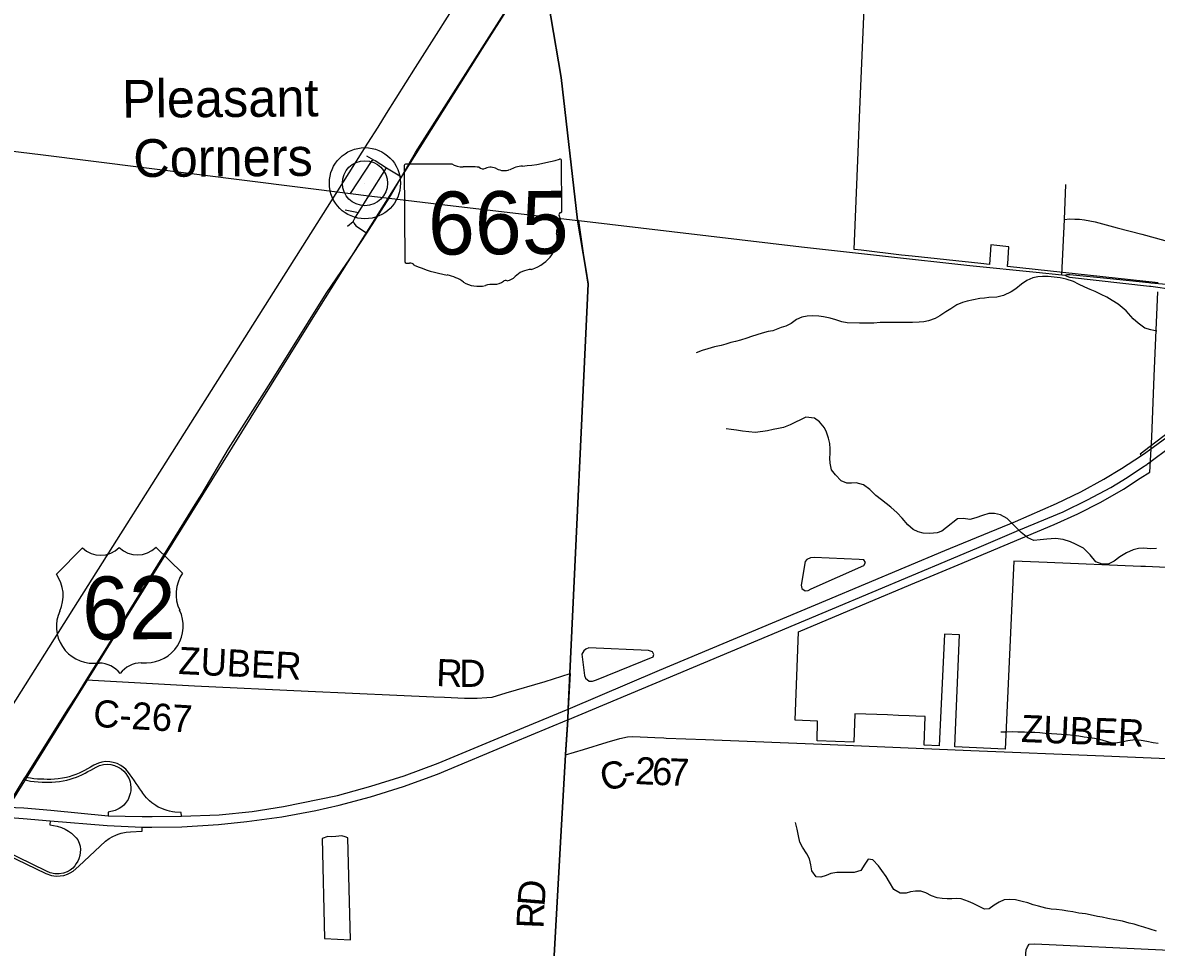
# Model space of a CAD drawing. Extents: x 114843 to 284848, y 317643 to 566895.
# Drawn here: x 166732 to 179255, y 335383 to 345598 of the extents above; entities that cross this region are included whole.
import ezdxf

# ---------------------------------------------------------------- set-up
doc = ezdxf.new("R2010")
doc.units = 0
for name, color, linetype in [('GM_X_City_Street', 7, 'Continuous'), ('GM_X_Corporation', 7, 'Continuous'), ('GM_X_County_Road', 7, 'Continuous'), ('GM_X_County_Road_Text', 7, 'Continuous'), ('GM_X_Interchange_Ramps', 7, 'Continuous'), ('GM_X_Interstate_Route', 7, 'Continuous'), ('GM_X_Minor_Lake', 7, 'Continuous'), ('GM_X_Minor_River', 7, 'Continuous'), ('GM_X_Rail_Line', 7, 'Continuous'), ('GM_X_State_Location', 7, 'Continuous'), ('GM_X_State_Route', 7, 'Continuous'), ('GM_X_State_Shield', 7, 'Continuous'), ('GM_X_Township', 7, 'Continuous'), ('GM_X_Township_Road', 7, 'Continuous'), ('GM_X_Township_Road_Text', 7, 'Continuous'), ('GM_X_Unincorporated', 7, 'Continuous'), ('GM_X_Unincorporated_Location', 7, 'Continuous'), ('GM_X_Unincorporated_Text', 7, 'Continuous'), ('GM_X_US_Location', 7, 'Continuous'), ('GM_X_US_Route', 7, 'Continuous'), ('GM_X_US_Shield', 7, 'Continuous')]:
    doc.layers.add(name, color=color, linetype=linetype)

msp = doc.modelspace()

# ---------------------------------------------------------------- linework, layer by layer
at = {"layer": 'GM_X_City_Street'}
for p, q in [((178240, 343425), (178254, 343810)), ((178210, 342812), (178240, 343425))]:
    msp.add_line(p, q, dxfattribs=at)
at = {"layer": 'GM_X_Corporation'}
for points in [[(179275, 342723), (177612, 342905), (177613, 342924), (177614, 342934), (177626, 343122), (177526, 343132), (177427, 343143), (177414, 342926), (177315, 342937), (176560, 343017), (176441, 343031), (175995, 343083), (175916, 343092), (175961, 344168), (175981, 344637), (176046, 346180), (176083, 346179), (176537, 346164), (177452, 346131), (178821, 346082), (178845, 346689), (178861, 347009), (179032, 347004), (180208, 346966)], [(179526, 339572), (179135, 339589), (179085, 339591), (178048, 339634), (177681, 339649), (177659, 339180), (177586, 337573), (177030, 337596), (177030, 337604), (177081, 338836), (176914, 338843), (176857, 337610), (176689, 337616), (176702, 337934), (176597, 337938), (176526, 337941), (176407, 337945), (176287, 337950), (176168, 337955), (176045, 337959), (175925, 337964), (175914, 337648), (175507, 337665), (175514, 337881), (175267, 337892), (175304, 338870), (176009, 339168), (176586, 339408), (176756, 339479), (177111, 339628), (177207, 339669), (178127, 340055), (178388, 340172), (178643, 340302), (178892, 340444), (179078, 340564), (179184, 340631), (179205, 341018), (179230, 341692), (179272, 342623)]]:
    msp.add_lwpolyline(points, dxfattribs=at)
at = {"layer": 'GM_X_County_Road'}
for points in [[(178240, 343425), (178295, 343429), (178356, 343428), (178405, 343427), (178462, 343420), (178520, 343410), (178578, 343398), (178823, 343331), (179095, 343260), (179709, 343093), (179953, 343027), (180080, 342994), (180111, 342980), (180149, 342963), (180181, 342944), (180258, 342894), (180262, 342897)], [(171391, 338146), (171613, 338137), (171754, 338134), (171858, 338143), (171920, 338146), (172074, 338193), (172505, 338319), (172779, 338408)], [(172779, 338408), (172760, 338015), (172754, 337897), (172728, 337511)], [(167438, 338338), (168631, 338273), (169885, 338211), (170864, 338170), (171275, 338150), (171391, 338146)], [(172728, 337511), (172928, 337570), (173188, 337651), (173328, 337689), (173413, 337707), (173472, 337711), (173717, 337700), (173816, 337696), (173842, 337695)], [(173842, 337695), (174275, 337678), (175652, 337624), (177207, 337559), (178674, 337497), (179461, 337466), (179852, 337451), (180056, 337436), (180116, 337440), (180152, 337456), (180170, 337475), (180182, 337517), (180188, 337600)]]:
    msp.add_lwpolyline(points, dxfattribs=at)
at = {"layer": 'GM_X_Interchange_Ramps'}
for points in [[(180038, 342582), (180035, 342561), (180095, 342550), (180152, 342521), (180218, 342475), (180262, 342409), (180281, 342330), (180277, 342274), (180261, 342221), (180225, 342128), (180166, 342003), (180160, 341992), (180123, 341918), (180067, 341819), (180011, 341725), (179862, 341524), (179758, 341390), (179627, 341267), (179514, 341164), (179327, 341021), (179189, 340917)], [(179189, 340917), (179076, 340832), (179093, 340815)], [(166750, 337243), (166773, 337229), (166817, 337220), (166860, 337215), (166905, 337212), (166946, 337209), (166984, 337208), (167024, 337207), (167056, 337208), (167096, 337210), (167139, 337215), (167181, 337222), (167221, 337230), (167258, 337240), (167291, 337250), (167326, 337261), (167353, 337272), (167385, 337288), (167421, 337307), (167452, 337324), (167484, 337341), (167543, 337374), (167580, 337390), (167626, 337402), (167665, 337405), (167707, 337401), (167747, 337392), (167788, 337375), (167819, 337356), (167850, 337329), (167872, 337305), (167892, 337275), (167908, 337244), (167919, 337212), (167925, 337180), (167928, 337147), (167926, 337112), (167921, 337083), (167910, 337048), (167896, 337017), (167886, 337000), (167866, 336973), (167849, 336955), (167826, 336935), (167799, 336917), (167777, 336905), (167753, 336896), (167678, 336876), (167676, 336835)], [(168487, 336831), (168484, 336871), (168415, 336876), (168386, 336880), (168356, 336886), (168328, 336893), (168296, 336904), (168268, 336915), (168230, 336933), (168205, 336948), (168181, 336963), (168158, 336981), (168133, 337002), (168111, 337024), (168099, 337036), (168083, 337055), (168060, 337085), (168048, 337104), (168028, 337133), (168008, 337162), (167987, 337191), (167967, 337221), (167941, 337259), (167920, 337288), (167901, 337316), (167871, 337350), (167844, 337374), (167816, 337393), (167777, 337412), (167733, 337426), (167694, 337433), (167649, 337434), (167608, 337428), (167571, 337418), (167543, 337407), (167518, 337394), (167481, 337372), (167447, 337355), (167415, 337338), (167386, 337322), (167355, 337306), (167321, 337291), (167287, 337280), (167246, 337267), (167215, 337260), (167172, 337251), (167126, 337244), (167083, 337239), (167042, 337237), (167003, 337237), (166967, 337239), (166933, 337240), (166897, 337242), (166856, 337246), (166818, 337250), (166792, 337255), (166767, 337271)], [(167037, 336781), (167034, 336737), (167114, 336720), (167163, 336706), (167202, 336689), (167239, 336668), (167272, 336643), (167303, 336615), (167323, 336592), (167341, 336569), (167356, 336534), (167366, 336500), (167370, 336463), (167369, 336430), (167365, 336398), (167354, 336362), (167342, 336336), (167325, 336309), (167309, 336283), (167287, 336259), (167258, 336237), (167224, 336217), (167183, 336204), (167135, 336195), (167087, 336196), (167035, 336207), (166994, 336223), (166353, 336537)], [(166303, 336530), (166337, 336513), (166989, 336199), (167051, 336177), (167101, 336170), (167148, 336171), (167188, 336178), (167228, 336191), (167257, 336205), (167289, 336225), (167354, 336281), (167646, 336555), (167686, 336584), (167729, 336607), (167761, 336623), (167786, 336632), (167822, 336644), (167877, 336655), (167925, 336659), (168053, 336667), (168053, 336709)]]:
    msp.add_lwpolyline(points, dxfattribs=at)
at = {"layer": 'GM_X_Interstate_Route'}
msp.add_line((168053, 336709), (168159, 336710), dxfattribs=at)
for points in [[(179140, 340850), (179222, 340910), (179425, 341061), (179601, 341208), (179742, 341340), (179914, 341507), (180114, 341723), (180323, 341972), (180491, 342200), (180586, 342339), (180683, 342491), (180715, 342545), (180731, 342572)], [(179197, 340753), (179387, 340892), (179555, 341027), (179716, 341164), (179856, 341295), (180015, 341447), (180213, 341675), (180422, 341925), (180590, 342152), (180685, 342292), (180757, 342406)], [(168162, 336829), (168487, 336831), (168904, 336847), (169266, 336884), (169614, 336937), (170209, 337060), (170578, 337163), (170947, 337278), (171321, 337416), (172163, 337766), (172760, 338015), (173768, 338443), (175604, 339215), (176919, 339767), (177699, 340087), (178151, 340286), (178420, 340415), (178677, 340555), (178870, 340672), (179093, 340815), (179140, 340850)], [(179150, 340718), (179159, 340724), (179197, 340753)], [(178885, 340545), (178944, 340581), (179103, 340686), (179150, 340718)], [(177297, 339804), (177737, 339990), (178226, 340195), (178494, 340325), (178752, 340464), (178885, 340545)], [(172744, 337893), (172754, 337897), (173843, 338352), (175679, 339124), (176994, 339676), (177297, 339804)], [(168159, 336710), (168492, 336713), (168894, 336738), (169207, 336772), (169594, 336826), (169970, 336894), (170228, 336954), (170573, 337045), (170941, 337160), (171316, 337297), (172157, 337648), (172744, 337893)], [(166560, 336932), (166744, 336924), (167043, 336899), (167676, 336835), (168054, 336828)], [(166407, 336833), (166495, 336825), (166738, 336806), (167037, 336781), (167667, 336729), (168053, 336709)], [(168054, 336828), (168059, 336828), (168162, 336829)]]:
    msp.add_lwpolyline(points, dxfattribs=at)
at = {"layer": 'GM_X_Minor_Lake'}
for points in [[(175474, 339688), (175434, 339684), (175394, 339669), (175376, 339644), (175331, 339382), (175339, 339348), (175375, 339320), (175409, 339326), (175441, 339344), (176024, 339602), (176042, 339634), (176026, 339664), (175974, 339668)], [(175974, 339668), (175474, 339688)], [(173697, 338591), (173705, 338617), (173689, 338649), (173647, 338661), (172987, 338690), (172953, 338678), (172933, 338660), (172911, 338622), (172938, 338387), (172948, 338355), (172990, 338325), (173026, 338323), (173072, 338337)], [(173072, 338337), (173697, 338591)], [(170323, 336592), (170295, 336604), (170259, 336613), (170191, 336607), (170145, 336602), (170105, 336606), (170042, 336584), (170065, 335480), (170354, 335467)], [(170354, 335467), (170323, 336592)]]:
    msp.add_lwpolyline(points, dxfattribs=at)
at = {"layer": 'GM_X_Minor_River'}
for points in [[(178397, 342709), (178339, 342737), (178261, 342765), (178193, 342779), (178061, 342795), (177997, 342793), (177947, 342789), (177892, 342780), (177826, 342750), (177766, 342710), (177702, 342658), (177650, 342624), (177568, 342584), (177494, 342566), (177406, 342562), (177356, 342556), (177304, 342550), (177234, 342536), (177166, 342520), (177116, 342506), (177051, 342482), (176985, 342438), (176931, 342402), (176865, 342358), (176811, 342330), (176739, 342304), (176687, 342294), (176635, 342288), (176563, 342286), (176455, 342286), (176383, 342285), (176205, 342285), (176135, 342279), (176084, 342277), (176032, 342277), (175976, 342277), (175840, 342281), (175782, 342293), (175714, 342314), (175652, 342334), (175580, 342348), (175526, 342356), (175460, 342358), (175398, 342354), (175340, 342344), (175282, 342318), (175220, 342276), (175164, 342246), (175110, 342230), (175020, 342194), (174966, 342186), (174901, 342168), (174841, 342148), (174783, 342130), (174731, 342112), (174663, 342092), (174607, 342077), (174555, 342065), (174499, 342047), (174447, 342033), (174373, 342015), (174301, 341995), (174237, 341977), (174173, 341951)], [(179261, 342190), (179195, 342203), (179128, 342223), (179053, 342277), (178999, 342325), (178921, 342413), (178833, 342488), (178767, 342528), (178709, 342564), (178647, 342596), (178579, 342626), (178523, 342650), (178465, 342677), (178397, 342709)], [(179115, 339794), (179057, 339790), (179001, 339774), (178927, 339740), (178852, 339696), (178788, 339648), (178722, 339614), (178656, 339614), (178586, 339642), (178524, 339720), (178450, 339793), (178364, 339835), (178306, 339863), (178226, 339889), (178142, 339899), (178046, 339893), (177972, 339885), (177904, 339876), (177836, 339908), (177764, 339964), (177658, 340070), (177608, 340122), (177534, 340159), (177466, 340177), (177404, 340177), (177334, 340155), (177262, 340129), (177196, 340109), (177126, 340119), (177060, 340115), (176936, 340019), (176885, 339979), (176835, 339961), (176753, 339953), (176679, 339957), (176625, 339973), (176569, 340000), (176511, 340052), (176447, 340124), (176393, 340184), (176323, 340244), (176272, 340287), (176220, 340325), (176158, 340373), (176090, 340441), (176020, 340493), (175940, 340514), (175888, 340512), (175836, 340512), (175774, 340538), (175712, 340602), (175668, 340656), (175652, 340730), (175650, 340786), (175652, 340839), (175654, 340891), (175648, 340947), (175634, 341009), (175612, 341073), (175588, 341123), (175536, 341189), (175478, 341230), (175384, 341240), (175324, 341210), (175270, 341184), (175212, 341156), (175138, 341126), (175080, 341116), (175022, 341104), (174960, 341088), (174908, 341080), (174824, 341072), (174754, 341076), (174684, 341084), (174616, 341095), (174558, 341103), (174502, 341111)], [(179259, 339789), (179193, 339784), (179115, 339794)], [(179277, 337633), (179219, 337641), (179149, 337655), (179087, 337667), (179023, 337675), (178941, 337665), (178889, 337653), (178827, 337643), (178773, 337640), (178705, 337658), (178631, 337678), (178573, 337690), (178521, 337698), (178457, 337706), (178399, 337716), (178341, 337722), (178271, 337730), (178207, 337735), (178155, 337737), (178097, 337741), (178027, 337745), (177967, 337751), (177915, 337755), (177851, 337757), (177799, 337759), (177727, 337761), (177671, 337763), (177605, 337761), (177536, 337761)], [(178718, 335703), (178656, 335715), (178604, 335725), (178524, 335742), (178472, 335752), (178400, 335762), (178334, 335774), (178278, 335784), (178216, 335792), (178154, 335800), (178092, 335806), (178036, 335816), (177952, 335839), (177896, 335853), (177836, 335873), (177772, 335891), (177698, 335909), (177638, 335913), (177576, 335909), (177520, 335883), (177465, 335847), (177409, 335807), (177357, 335805), (177297, 335835), (177233, 335868), (177179, 335890), (177099, 335920), (177047, 335924), (176997, 335920), (176945, 335918), (176889, 335922), (176833, 335930), (176771, 335950), (176711, 335985), (176655, 336005), (176595, 336005), (176541, 335997), (176491, 335983), (176425, 335981), (176355, 336021), (176307, 336103), (176271, 336164), (176223, 336232), (176185, 336282), (176125, 336348), (176073, 336358), (176037, 336300), (175991, 336230), (175919, 336208), (175855, 336208), (175805, 336210), (175727, 336210), (175659, 336197), (175607, 336177), (175551, 336159), (175499, 336161), (175449, 336229), (175439, 336293), (175423, 336359), (175395, 336415), (175345, 336490), (175319, 336544), (175301, 336614), (175287, 336688), (175269, 336762)], [(179256, 335562), (179188, 335584), (179118, 335606), (179066, 335621), (179010, 335637), (178956, 335651), (178882, 335671), (178798, 335687), (178718, 335703)]]:
    msp.add_lwpolyline(points, dxfattribs=at)
at = {"layer": 'GM_X_Rail_Line'}
for points in [[(196042, 380964), (194033, 377563), (193868, 377325), (192058, 375431), (190340, 374235), (188290, 370932), (187383, 369296), (186211, 367714), (185191, 366327), (183802, 363991), (182496, 361740), (179755, 357653), (178698, 356015), (176027, 351942), (171808, 345313), (170010, 342459), (166009, 336034), (165560, 335288), (165458, 335042), (165305, 334516), (164243, 330883)], [(165560, 336379), (167342, 339200), (168589, 341173), (170215, 343741), (170545, 344266), (170658, 344443), (170753, 344594), (171071, 345103), (171658, 346027), (171787, 346235), (172464, 347303), (173962, 349676), (174698, 350836), (175401, 351957), (175709, 352436), (176672, 353966), (176952, 354405), (177651, 355520)]]:
    msp.add_lwpolyline(points, dxfattribs=at)
at = {"layer": 'GM_X_State_Route'}
for p, q in [((170781, 343660), (170917, 343893)), ((170533, 343273), (170781, 343660)), ((179195, 342685), (179247, 342678)), ((166750, 337243), (166767, 337271)), ((166592, 336984), (166750, 337243))]:
    msp.add_line(p, q, dxfattribs=at)
for points in [[(170917, 343893), (171073, 344163), (172441, 346316)], [(161581, 345594), (161846, 345387), (162609, 344810), (162702, 344748), (162782, 344699), (162868, 344661), (162967, 344625), (163115, 344590), (163234, 344565), (163417, 344541), (165040, 344369), (166930, 344140), (170354, 343709), (170556, 343684), (170781, 343660)], [(170781, 343660), (171332, 343593), (172864, 343414), (172875, 343413)], [(172875, 343413), (175336, 343121), (176262, 343018), (177197, 342914), (177927, 342841)], [(168637, 340273), (168715, 340398), (169007, 340890), (169498, 341665), (170086, 342607), (170258, 342859), (170388, 343049), (170533, 343273)], [(177927, 342841), (178210, 342812), (178246, 342809)], [(178246, 342809), (178271, 342817), (178300, 342815), (178744, 342773), (179172, 342727), (179193, 342725)], [(178246, 342809), (178268, 342797), (178296, 342787), (179179, 342687), (179195, 342685)], [(179193, 342725), (179664, 342683), (180045, 342649), (180509, 342600)], [(179247, 342678), (179547, 342636), (179774, 342611)], [(167438, 338338), (167645, 338664), (167805, 338930), (168341, 339794), (168637, 340273)], [(166767, 337271), (167234, 338018), (167326, 338156), (167438, 338338)]]:
    msp.add_lwpolyline(points, dxfattribs=at)
at = {"layer": 'GM_X_State_Shield'}
for p, q in [((170946, 344014), (170953, 342958)), ((171472, 344036), (170963, 344033)), ((172690, 343519), (172686, 344071)), ((172690, 343519), (172690, 343519))]:
    msp.add_line(p, q, dxfattribs=at)
for centre, major_axis, ratio, start_param, end_param in [((170966, 344017), (20.2, 0.1), 0.8, 1.712693, 3.28349), ((171593, 344160), (196, 1), 0.8, 4.042523, 4.731795), ((171663, 343445), (702, 5), 0.8, 1.404758, 1.657858), ((172304, 343720), (371, 3), 0.8, 1.699011, 2.107814), ((172056, 345481), (1846, 13), 0.800001, 4.814395, 5.04237), ((172666, 344074), (19.4, 0.1), 0.8, 6.141152, 7.989035), ((171818, 344029), (56.4, 0.4), 0.8, 3.836095, 5.185415), ((171902, 343907), (117, 1), 0.8, 0.950623, 2.079405), ((172052, 344076), (141, 1), 0.8, 4.081561, 5.145723), ((172669, 343516), (20.7, 0.1), 0.8, 5.05454, 6.418171), ((172686, 343478), (30, 0.2), 0.8, 1.883978, 3.671073), ((172495, 343407), (180, 1), 0.8, 5.934695, 6.695948), ((172175, 343213), (462, 3), 0.8, 5.101753, 6.440018), ((172761, 343288), (131, 1), 0.8, 2.387724, 3.262537), ((170973, 342956), (20.3, 0.1), 0.8, 3.00124, 4.508301), ((170976, 343064), (155, 1), 0.8, 4.665946, 4.897461), ((171009, 342897), (56, 0.4), 0.8, 0.519207, 1.627899), ((171709, 343852), (1333, 10), 0.8, 4.195996, 4.48896), ((171321, 342486), (417, 3), 0.8, 0.823519, 1.323588), ((172052, 342863), (149, 1), 0.8, 4.937069, 5.64225), ((172374, 342671), (253, 2), 0.8, 1.647645, 2.488434), ((171769, 342897), (265, 2), 0.8, 4.026481, 4.996735), ((171925, 342533), (217, 2), 0.8, 1.495662, 1.94098), ((171942, 342820), (141, 1), 0.8, 4.691044, 5.507374), ((172070, 342718), (39.7, 0.3), 0.8, 1.147584, 2.315152)]:
    msp.add_ellipse(centre, major_axis=major_axis, ratio=ratio, start_param=start_param, end_param=end_param, dxfattribs=at)
at = {"layer": 'GM_X_Township'}
for points in [[(172451, 346337), (172681, 344992), (172863, 343417), (172954, 342875), (172978, 342712), (172778, 338411), (172759, 338018), (172753, 337899), (172727, 337514), (172727, 337511), (172677, 336606), (172473, 332991), (172412, 331756), (172407, 331608), (172361, 330680), (171077, 330708), (167555, 330803), (166612, 330827)], [(181070, 330253), (177726, 330436), (177559, 330442), (172361, 330680), (172407, 331608), (172412, 331756), (172473, 332991), (172677, 336606), (172727, 337511), (172727, 337514), (172753, 337899), (172759, 338018), (172778, 338411), (172978, 342712), (172954, 342875), (172863, 343417), (172681, 344992), (172451, 346337)]]:
    msp.add_lwpolyline(points, dxfattribs=at)
at = {"layer": 'GM_X_Township_Road'}
for p, q in [((170296, 343530), (170443, 343502)), ((172779, 338408), (172806, 338982)), ((172694, 336881), (172728, 337511))]:
    msp.add_line(p, q, dxfattribs=at)
for points in [[(170354, 343709), (170594, 344075), (170609, 344083)], [(170529, 344125), (170609, 344083), (170628, 344076), (170752, 343994), (170917, 343893)], [(170320, 343350), (170383, 343400), (170400, 343438), (170443, 343502), (170556, 343684), (170752, 343994)], [(170383, 343400), (170393, 343379), (170414, 343353), (170452, 343329), (170533, 343273)], [(172806, 338982), (172980, 342709), (172955, 342872), (172875, 343413)], [(172728, 337511), (172754, 337897), (172760, 338015), (172779, 338408)], [(177774, 334097), (177775, 334129), (177807, 335026), (177815, 335315), (177819, 335357), (177831, 335387), (177852, 335419), (177912, 335422), (179323, 335354), (179365, 335353), (179391, 335367), (179395, 335397), (179461, 337466)], [(172410, 331675), (172414, 331754), (172474, 332988), (172679, 336603), (172694, 336881)]]:
    msp.add_lwpolyline(points, dxfattribs=at)
at = {"layer": 'GM_X_Unincorporated'}
for radius in [393, 249]:
    msp.add_circle((170513, 343824), radius, dxfattribs=at)
at = {"layer": 'GM_X_Unincorporated_Location'}
msp.add_line((170513, 343824), (170513, 343824), dxfattribs=at)
at = {"layer": 'GM_X_US_Route'}
for p, q in [((170781, 343660), (170917, 343893)), ((170533, 343273), (170781, 343660)), ((166750, 337243), (166767, 337271)), ((166592, 336984), (166750, 337243))]:
    msp.add_line(p, q, dxfattribs=at)
for points in [[(170917, 343893), (171073, 344163), (172441, 346316)], [(168637, 340273), (168715, 340398), (169007, 340890), (169498, 341665), (170086, 342607), (170258, 342859), (170388, 343049), (170533, 343273)], [(167438, 338338), (167645, 338664), (167805, 338930), (168341, 339794), (168637, 340273)], [(166767, 337271), (167234, 338018), (167326, 338156), (167438, 338338)]]:
    msp.add_lwpolyline(points, dxfattribs=at)
at = {"layer": 'GM_X_US_Shield'}
for p, q in [((167393, 339797), (167105, 339505)), ((168498, 339515), (168205, 339803)), ((167518, 338521), (167576, 338522)), ((168041, 338525), (168099, 338526))]:
    msp.add_line(p, q, dxfattribs=at)
for centre, radius, start, end in [((167595, 340005), 290, 225.9855, 314.8395), ((168001, 340008), 290, 225.9855, 314.8395), ((166774, 339269), 406, 334.9596, 35.4134), ((168832, 339284), 406, 145.4116, 205.8654), ((167511, 338927), 406, 155.2444, 271.0508), ((168100, 338932), 406, 269.7743, 25.5806), ((167579, 338232), 290, 37.2824, 90.4125), ((168043, 338235), 290, 90.4125, 143.5426)]:
    msp.add_arc(centre, radius, start, end, dxfattribs=at)

# ---------------------------------------------------------------- texts
at = {"layer": 'GM_X_County_Road_Text'}
for s, rotation, p in [('ZUBER', 357.291, (168448, 338403)), ('R', 357.7303, (171297, 338270)), ('D', 0.0233, (171556, 338260)), ('C-267', 356.5619, (167506, 337820)), ('ZUBER', 357.7049, (177757, 337652)), ('C', 16.0621, (173161, 337100)), ('2', 357.1924, (173493, 337188)), ('6', 357.7729, (173681, 337179)), ('7', 358.0547, (173868, 337172)), ('-', 10.8323, (173391, 337167))]:
    msp.add_text(s, height=300, rotation=rotation, dxfattribs=at).set_placement(p)
at = {"layer": 'GM_X_State_Location'}
for s, p in [('s', (171801, 343422)), ('r', (171801, 343422)), ('665', (171448, 343347))]:
    msp.add_text(s, height=1, rotation=0.4126, dxfattribs=at).set_placement(p)
at = {"layer": 'GM_X_State_Shield'}
msp.add_text('665', height=696.1, rotation=0.4126, dxfattribs=at).set_placement((171212, 343034))
at = {"layer": 'GM_X_Township_Road_Text'}
for s, rotation, p in [('D', 85.4413, (172496, 335829)), ('R', 87.6638, (172486, 335586))]:
    msp.add_text(s, height=300, rotation=rotation, dxfattribs=at).set_placement(p)
at = {"layer": 'GM_X_Unincorporated_Text'}
for s, p in [('Pleasant', (167831, 344547)), ('Corners', (167955, 343892))]:
    msp.add_text(s, height=417, rotation=0.4125, dxfattribs=at).set_placement(p)
at = {"layer": 'GM_X_US_Location'}
for s, p in [('0', (167804, 339127)), ('/', (167804, 339127)), ('62', (167599, 338919))]:
    msp.add_text(s, height=1, rotation=0.4125, dxfattribs=at).set_placement(p)
at = {"layer": 'GM_X_US_Shield'}
msp.add_text('62', height=696.1, rotation=0.4125, dxfattribs=at).set_placement((167391, 338782))

doc.saveas('drawing.dxf')
